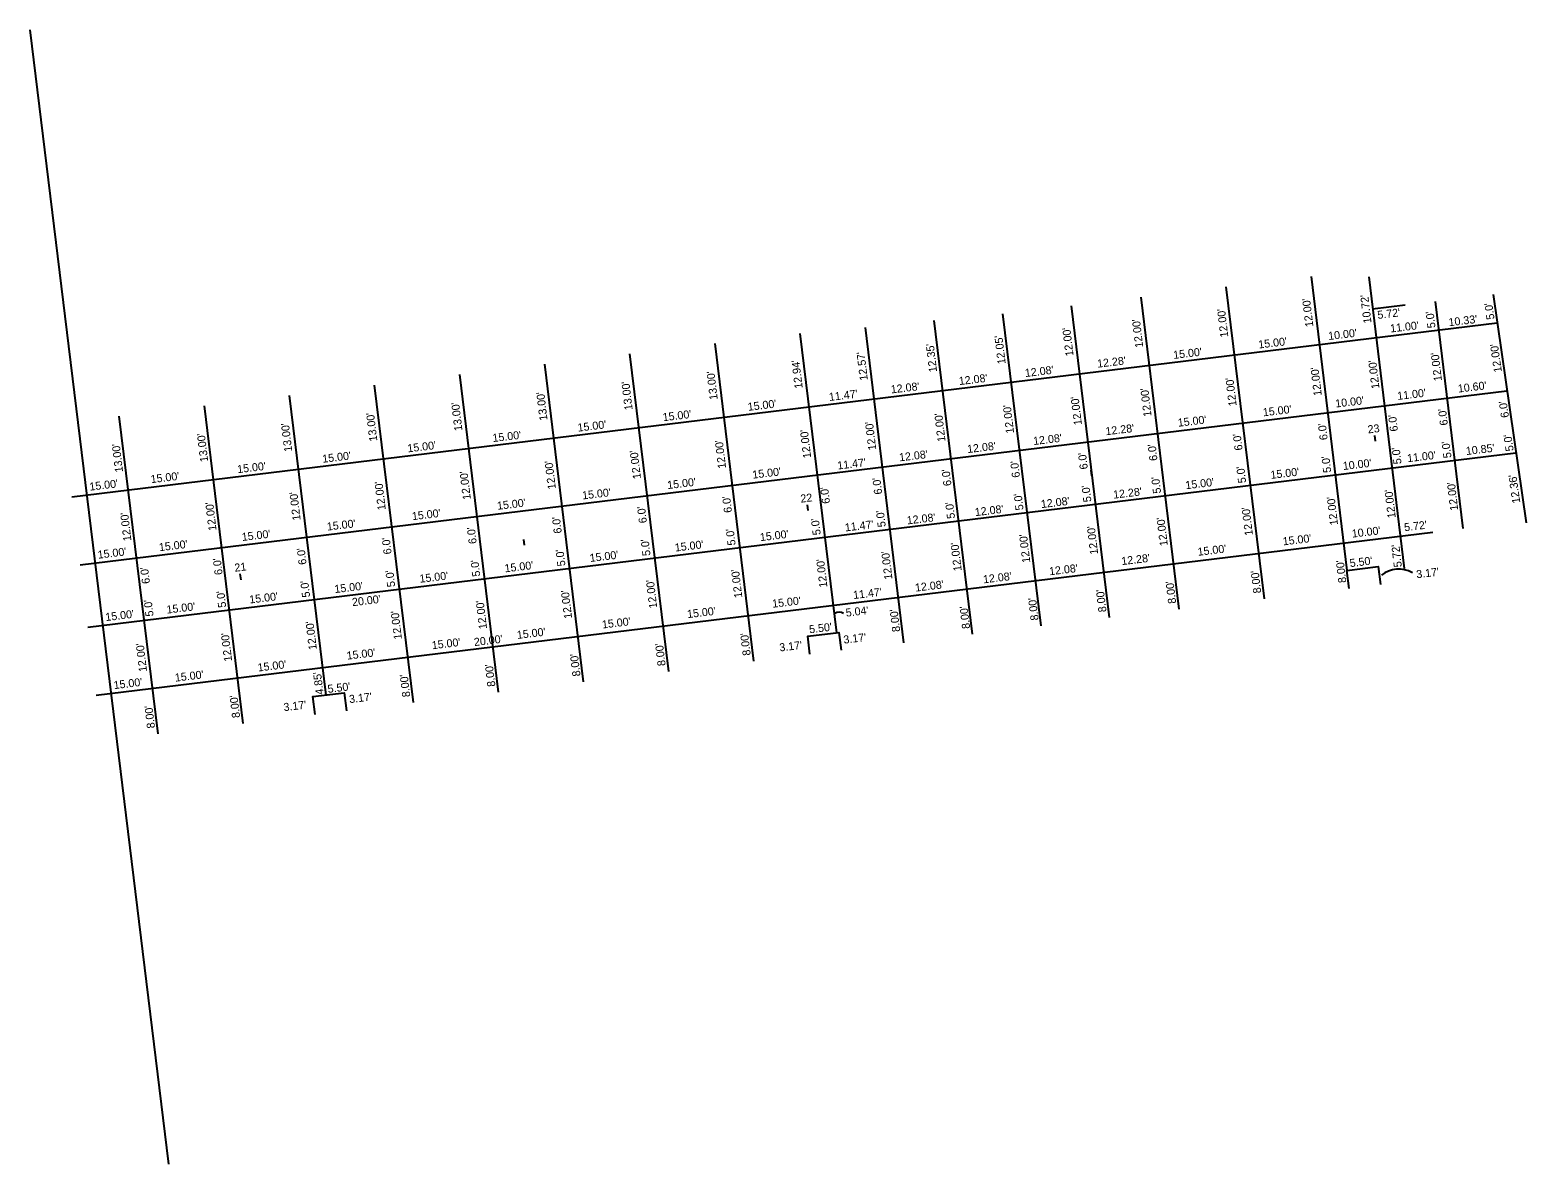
# Model space of a CAD drawing. Extents: x 1828119 to 1831197, y 711744 to 712285.
# Drawn here: x 1828290.3 to 1828552.1, y 711744.1 to 711942.7 of the extents above; entities that cross this region are included whole.
import ezdxf

# ---------------------------------------------------------------- set-up
doc = ezdxf.new("R2010")
doc.units = 0
for name, color, linetype in [('DR_X_Cells', 7, 'Continuous'), ('PM_P_Crosswalk', 7, 'Continuous'), ('PM_X_Lane_Line', 7, 'Continuous'), ('SG_X_Controllers', 7, 'Continuous'), ('SN_X_Public', 7, 'Continuous'), ('UT_X_Telecom', 7, 'Continuous')]:
    doc.layers.add(name, color=color, linetype=linetype)

msp = doc.modelspace()

# ---------------------------------------------------------------- linework, layer by layer
at = {"layer": 'DR_X_Cells'}
for p, q in [((1828514.43, 711899.52), (1828520.71, 711848.07)), ((1828524.51, 711899.46), (1828530.74, 711848.4)), ((1828499.54, 711897.7), (1828506.2, 711843.1)), ((1828472.46, 711894.39), (1828479.12, 711839.8)), ((1828484.65, 711895.88), (1828491.31, 711841.29)), ((1828530.88, 711894.47), (1828525.2, 711893.78)), ((1828536.12, 711895.11), (1828540.97, 711855.41)), ((1828297.6, 711860.95), (1828546.98, 711891.4)), ((1828448.43, 711891.82), (1828455.14, 711836.87)), ((1828460.46, 711892.98), (1828467.13, 711838.33)), ((1828424.98, 711889.54), (1828431.37, 711837.16)), ((1828436.41, 711890.56), (1828443.14, 711835.4)), ((1828410.08, 711887.78), (1828416.87, 711832.2)), ((1828380.3, 711884.15), (1828387.09, 711828.56)), ((1828395.19, 711885.97), (1828401.98, 711830.38)), ((1828365.41, 711882.33), (1828372.2, 711826.74)), ((1828299.05, 711849.04), (1828548.7, 711879.52)), ((1828335.63, 711878.69), (1828342.04, 711826.24)), ((1828350.52, 711880.51), (1828357.31, 711824.92)), ((1828320.74, 711876.88), (1828327.53, 711821.29)), ((1828305.85, 711875.06), (1828312.64, 711819.47)), ((1828300.39, 711838.12), (1828550.28, 711868.63)), ((1828301.84, 711826.21), (1828535.73, 711854.77))]:
    msp.add_line(p, q, dxfattribs=at)
for points in [[(1828521.09, 711844.92), (1828520.71, 711848.07), (1828526.17, 711848.73), (1828526.55, 711845.59)], [(1828426.73, 711833.4), (1828426.35, 711836.54), (1828431.81, 711837.21), (1828432.19, 711834.07)], [(1828340.17, 711822.83), (1828339.78, 711825.97), (1828345.24, 711826.64), (1828345.63, 711823.5)]]:
    msp.add_lwpolyline(points, dxfattribs=at)
at = {"layer": 'PM_P_Crosswalk'}
msp.add_line((1828546.27, 711896.35), (1828552.05, 711856.4), dxfattribs=at)
at = {"layer": 'SG_X_Controllers'}
msp.add_line((1828290.26, 711942.67), (1828314.5, 711744.14), dxfattribs=at)
at = {"layer": 'SN_X_Public'}
for p, q in [((1828525.73, 711870.67), (1828525.6, 711871.67)), ((1828476.09, 711864.61), (1828475.97, 711865.61)), ((1828426.46, 711858.55), (1828426.34, 711859.55)), ((1828376.83, 711852.49), (1828376.71, 711853.49)), ((1828327.2, 711846.43), (1828327.08, 711847.43))]:
    msp.add_line(p, q, dxfattribs=at)
at = {"layer": 'UT_X_Telecom'}
for centre, radius, start, end in [((1828529.75, 711843.4), 4.88, 60.3627, 128.292), ((1828431.87, 711839.44), 1.33, 55.503, 125.0004)]:
    msp.add_arc(centre, radius, start, end, dxfattribs=at)

# ---------------------------------------------------------------- texts
at = {"layer": 'PM_X_Lane_Line'}
for p in [(1828346.71, 711841.79), (1828368.04, 711834.81)]:
    msp.add_text("20.00'", height=1.4, rotation=6.7772, dxfattribs=at).set_placement(p)
at = {"layer": 'SN_X_Public'}
for s, p in [('23', (1828524.42, 711872.03)), ('22', (1828425.17, 711859.91)), ('21', (1828326.14, 711847.82))]:
    msp.add_text(s, height=1.4, rotation=6.9614, dxfattribs=at).set_placement(p)
at = {"layer": 'UT_X_Telecom'}
for s, rotation, p in [("12.00'", 96.7772, (1828514.84, 711890.75)), ("10.72'", 96.7772, (1828525.01, 711891.38)), ("5.0'", 98.2381, (1828546.54, 711892.05)), ("12.00'", 96.7772, (1828485.07, 711887.12)), ("12.00'", 96.7772, (1828499.96, 711888.93)), ("5.72'", 6.7772, (1828526.11, 711892.07)), ("11.00'", 6.7772, (1828528.35, 711889.7)), ("5.0'", 96.7772, (1828536.21, 711890.54)), ("10.33'", 6.7772, (1828538.57, 711890.79)), ("12.05'", 96.7772, (1828461, 711884.24)), ("12.00'", 96.7772, (1828472.88, 711885.63)), ("15.00'", 6.7772, (1828505.28, 711886.89)), ("10.00'", 6.7772, (1828517.51, 711888.38)), ("12.57'", 96.7772, (1828436.88, 711881.38)), ("12.35'", 96.7772, (1828449, 711882.83)), ("15.00'", 6.7772, (1828490.39, 711885.07)), ("12.00'", 98.2381, (1828547.83, 711882.82)), ("12.94'", 96.7772, (1828425.49, 711879.96)), ("12.08'", 6.7772, (1828464.44, 711881.9)), ("12.28'", 6.7772, (1828477.09, 711883.54)), ("12.00'", 96.7772, (1828516.31, 711878.69)), ("12.00'", 96.7772, (1828526.41, 711879.92)), ("12.00'", 96.7772, (1828537.34, 711881.26)), ("13.00'", 96.7772, (1828395.73, 711876.19)), ("13.00'", 96.7772, (1828410.62, 711878)), ("12.08'", 6.7772, (1828440.98, 711879.03)), ("12.08'", 6.7772, (1828452.88, 711880.49)), ("12.00'", 96.7772, (1828501.42, 711876.87)), ("10.60'", 6.7772, (1828540.2, 711879.18)), ("13.00'", 96.7772, (1828380.84, 711874.37)), ("11.47'", 6.7772, (1828430.15, 711877.71)), ("12.00'", 96.7772, (1828474.34, 711873.56)), ("12.00'", 96.7772, (1828486.53, 711875.05)), ("10.00'", 6.7772, (1828518.75, 711876.56)), ("11.00'", 6.7772, (1828529.59, 711877.89)), ("13.00'", 96.7772, (1828365.95, 711872.55)), ("15.00'", 6.7772, (1828401.06, 711874.16)), ("15.00'", 6.7772, (1828415.94, 711875.98)), ("12.00'", 96.7772, (1828462.47, 711872.11)), ("15.00'", 6.7772, (1828506.08, 711875.02)), ("6.0'", 96.7772, (1828538.38, 711873.51)), ("6.0'", 98.2381, (1828549.07, 711874.88)), ("13.00'", 96.7772, (1828336.17, 711868.91)), ("13.00'", 96.7772, (1828351.06, 711870.73)), ("15.00'", 6.7772, (1828386.17, 711872.34)), ("12.00'", 96.7772, (1828438.36, 711869.17)), ("12.00'", 96.7772, (1828450.48, 711870.65)), ("12.28'", 6.7772, (1828478.54, 711871.71)), ("15.00'", 6.7772, (1828491.19, 711873.2)), ("6.0'", 96.7772, (1828517.35, 711870.95)), ("6.0'", 96.7772, (1828529.64, 711872.45)), ("13.00'", 96.7772, (1828321.46, 711867.12)), ("15.00'", 6.7772, (1828356.39, 711868.71)), ("15.00'", 6.7772, (1828371.28, 711870.52)), ("12.00'", 96.7772, (1828412.08, 711865.96)), ("12.00'", 96.7772, (1828426.97, 711867.78)), ("12.08'", 6.7772, (1828454.34, 711868.59)), ("12.08'", 6.7772, (1828465.89, 711870)), ("6.0'", 96.7772, (1828502.46, 711869.13)), ("5.0'", 96.7772, (1828539, 711867.79)), ("5.0'", 98.2381, (1828549.89, 711869.01)), ("13.00'", 96.7772, (1828306.57, 711865.3)), ("15.00'", 6.7772, (1828341.5, 711866.89)), ("12.00'", 96.7772, (1828397.19, 711864.14)), ("12.08'", 6.7772, (1828442.43, 711867.14)), ("6.0'", 96.7772, (1828475.38, 711865.82)), ("6.0'", 96.7772, (1828487.57, 711867.31)), ("5.0'", 96.7772, (1828517.97, 711865.22)), ("5.0'", 96.7772, (1828530.27, 711866.72)), ("11.00'", 6.7772, (1828531.32, 711866.99)), ("10.85'", 6.7772, (1828541.6, 711868.25)), ("15.00'", 6.7772, (1828311.47, 711863.32)), ("15.00'", 6.7772, (1828326.61, 711865.07)), ("12.00'", 96.7772, (1828367.42, 711860.51)), ("12.00'", 96.7772, (1828382.3, 711862.33)), ("15.00'", 6.7772, (1828416.75, 711864.11)), ("11.47'", 6.7772, (1828431.62, 711865.71)), ("6.0'", 96.7772, (1828451.52, 711862.91)), ("6.0'", 96.7772, (1828463.51, 711864.37)), ("5.0'", 96.7772, (1828503.08, 711863.4)), ("15.00'", 6.7772, (1828507.41, 711864.07)), ("10.00'", 6.7772, (1828520.07, 711865.62)), ("15.00'", 6.7772, (1828300.75, 711862.01)), ("12.00'", 96.7772, (1828352.53, 711858.69)), ("15.00'", 6.7772, (1828401.86, 711862.29)), ("6.0'", 96.7772, (1828430.27, 711859.81)), ("6.0'", 96.7772, (1828439.4, 711861.43)), ("5.0'", 96.7772, (1828476, 711860.09)), ("12.28'", 6.7772, (1828479.89, 711860.61)), ("5.0'", 96.7772, (1828488.19, 711861.58)), ("15.00'", 6.7772, (1828492.52, 711862.26)), ("12.00'", 96.7772, (1828540.18, 711858.61)), ("12.36'", 98.2381, (1828551.05, 711859.91)), ("12.00'", 96.7772, (1828337.64, 711856.87)), ("15.00'", 6.7772, (1828372.08, 711858.66)), ("15.00'", 6.7772, (1828386.97, 711860.47)), ("6.0'", 96.7772, (1828413.12, 711858.22)), ("5.0'", 96.7772, (1828464.13, 711858.65)), ("12.08'", 6.7772, (1828467.24, 711858.96)), ("12.00'", 96.7772, (1828519.15, 711856.04)), ("12.00'", 96.7772, (1828529.25, 711857.28)), ("12.00'", 96.7772, (1828308.03, 711853.26)), ("12.00'", 96.7772, (1828322.92, 711855.08)), ("15.00'", 6.7772, (1828357.19, 711856.84)), ("6.0'", 96.7772, (1828383.34, 711854.58)), ("6.0'", 96.7772, (1828398.23, 711856.4)), ("5.0'", 96.7772, (1828440.02, 711855.7)), ("12.08'", 6.7772, (1828443.78, 711856.1)), ("5.0'", 96.7772, (1828452.14, 711857.18)), ("12.08'", 6.7772, (1828455.68, 711857.55)), ("12.00'", 96.7772, (1828504.26, 711854.23)), ("15.00'", 6.7772, (1828327.41, 711853.2)), ("15.00'", 6.7772, (1828342.3, 711855.02)), ("6.0'", 96.7772, (1828368.45, 711852.77)), ("5.0'", 96.7772, (1828413.75, 711852.49)), ("15.00'", 6.7772, (1828418.07, 711853.17)), ("5.0'", 96.7772, (1828428.64, 711854.31)), ("11.47'", 6.7772, (1828432.94, 711854.87)), ("12.00'", 96.7772, (1828477.18, 711850.92)), ("12.00'", 96.7772, (1828489.37, 711852.41)), ("10.00'", 6.7772, (1828521.64, 711853.79)), ("5.72'", 6.7772, (1828530.8, 711854.9)), ("15.00'", 6.7772, (1828302.2, 711850.1)), ("15.00'", 6.7772, (1828312.92, 711851.41)), ("6.0'", 96.7772, (1828353.56, 711850.95)), ("5.0'", 96.7772, (1828398.86, 711850.67)), ("15.00'", 6.7772, (1828403.18, 711851.35)), ("12.00'", 96.7772, (1828453.31, 711848.01)), ("12.00'", 96.7772, (1828465.31, 711849.47)), ("15.00'", 6.7772, (1828494.66, 711850.61)), ("15.00'", 6.7772, (1828509.55, 711852.43)), ("5.72'", 96.7772, (1828530.33, 711848.69)), ("6.0'", 96.7772, (1828323.99, 711847.34)), ("6.0'", 96.7772, (1828338.68, 711849.13)), ("5.0'", 96.7772, (1828369.08, 711847.04)), ("15.00'", 6.7772, (1828373.4, 711847.71)), ("5.0'", 96.7772, (1828383.97, 711848.86)), ("15.00'", 6.7772, (1828388.29, 711849.53)), ("12.00'", 96.7772, (1828429.81, 711845.14)), ("12.00'", 96.7772, (1828441.19, 711846.53)), ("12.28'", 6.7772, (1828481.31, 711848.98)), ("8.00'", 96.7772, (1828520.61, 711845.95)), ("5.50'", 6.7772, (1828521.27, 711848.63)), ("6.0'", 96.7772, (1828311.28, 711845.79)), ("5.0'", 96.7772, (1828354.19, 711845.22)), ("15.00'", 6.7772, (1828358.51, 711845.89)), ("12.00'", 96.7772, (1828414.92, 711843.32)), ("12.08'", 6.7772, (1828457.12, 711845.79)), ("12.08'", 6.7772, (1828468.68, 711847.2)), ("8.00'", 96.7772, (1828505.72, 711844.13)), ("3.17'", 6.7772, (1828532.92, 711846.68)), ("5.0'", 96.7772, (1828324.62, 711841.61)), ("15.00'", 6.7772, (1828328.73, 711842.26)), ("5.0'", 96.7772, (1828339.3, 711843.4)), ("15.00'", 6.7772, (1828343.62, 711844.08)), ("12.00'", 96.7772, (1828385.14, 711839.68)), ("12.00'", 96.7772, (1828400.03, 711841.5)), ("11.47'", 6.7772, (1828434.38, 711843.04)), ("12.08'", 6.7772, (1828445.22, 711844.34)), ("8.00'", 96.7772, (1828478.64, 711840.82)), ("8.00'", 96.7772, (1828490.83, 711842.31)), ("5.0'", 96.7772, (1828311.91, 711840.06)), ("15.00'", 6.7772, (1828314.25, 711840.49)), ("12.00'", 96.7772, (1828370.25, 711837.86)), ("15.00'", 6.7772, (1828405.33, 711839.7)), ("15.00'", 6.7772, (1828420.22, 711841.52)), ("5.04'", 6.7772, (1828433.09, 711839.95)), ("8.00'", 96.7772, (1828454.78, 711837.91)), ("8.00'", 96.7772, (1828466.77, 711839.37)), ("15.00'", 6.7772, (1828303.54, 711839.18)), ("12.00'", 96.7772, (1828340.47, 711834.23)), ("12.00'", 96.7772, (1828355.36, 711836.05)), ("15.00'", 6.7772, (1828390.44, 711837.88)), ("8.00'", 96.7772, (1828442.55, 711837.37)), ("12.00'", 96.7772, (1828325.65, 711832.2)), ("15.00'", 6.7772, (1828375.55, 711836.06)), ("8.00'", 96.7772, (1828416.39, 711833.22)), ("5.50'", 6.7772, (1828426.69, 711837.04)), ("3.17'", 6.7772, (1828432.69, 711835.23)), ("12.00'", 96.7772, (1828310.76, 711830.38)), ("15.00'", 6.7772, (1828345.77, 711832.43)), ("15.00'", 6.7772, (1828360.66, 711834.25)), ("8.00'", 96.7772, (1828401.5, 711831.4)), ("3.17'", 6.7772, (1828421.48, 711833.86)), ("15.00'", 6.7772, (1828330.19, 711830.35)), ("8.00'", 96.7772, (1828371.72, 711827.77)), ("8.00'", 96.7772, (1828386.61, 711829.58)), ("15.00'", 6.7772, (1828304.99, 711827.27)), ("15.00'", 6.7772, (1828315.71, 711828.58)), ("4.85'", 96.7772, (1828341.66, 711826.39)), ("8.00'", 96.7772, (1828356.83, 711825.95)), ("8.00'", 96.7772, (1828327.05, 711822.31)), ("5.50'", 6.7772, (1828342.43, 711826.61)), ("3.17'", 6.7772, (1828346.2, 711824.82)), ("8.00'", 96.7772, (1828312.16, 711820.49)), ("3.17'", 6.7772, (1828334.72, 711823.41))]:
    msp.add_text(s, height=1.4, rotation=rotation, dxfattribs=at).set_placement(p)

doc.saveas('drawing.dxf')
